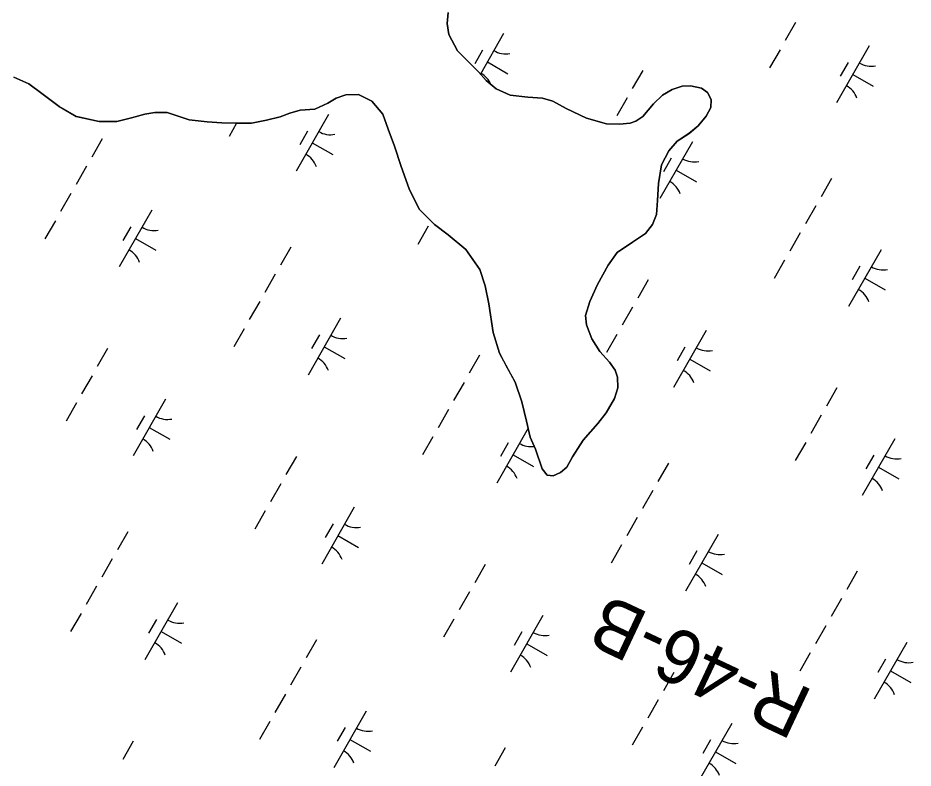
# Model space of a CAD drawing. Extents: x 3930721 to 3950824, y 220441 to 242861.
# Drawn here: x 3936788 to 3937473, y 225396 to 225970 of the extents above; entities that cross this region are included whole.
import ezdxf

# ---------------------------------------------------------------- set-up
doc = ezdxf.new("R2010")
doc.units = 0
for name, color, linetype in [('V-RIVR-RANG-IDEN', 7, 'Continuous'), ('V-TOPO-SHOR', 7, 'Continuous'), ('V-WETL-SWMP', 7, 'Continuous')]:
    doc.layers.add(name, color=color, linetype=linetype)

msp = doc.modelspace()

# ---------------------------------------------------------------- linework, layer by layer
at = {"layer": 'V-TOPO-SHOR'}
for points in [[(3937177.41, 225661.28), (3937180.22, 225648.96), (3937184.22, 225639.84), (3937189.42, 225624.75), (3937193.02, 225619.99), (3937197.79, 225619.6), (3937203.34, 225622), (3937208.1, 225625.99), (3937212.45, 225633.95), (3937220.76, 225646.69), (3937231.85, 225659.44), (3937238.19, 225667.8), (3937244.52, 225678.54), (3937247.28, 225686.9), (3937246.86, 225694.84), (3937245.25, 225700.4), (3937240.87, 225706.35), (3937233.29, 225714.67), (3937227.31, 225724.2), (3937223.3, 225734.92), (3937222.49, 225742.06), (3937225.64, 225752.8), (3937231.57, 225765.93), (3937239.87, 225780.66), (3937246.6, 225790.21), (3937258.5, 225798.19), (3937268.42, 225804.98), (3937273.57, 225811.74), (3937276.73, 225819.3), (3937277.49, 225830.03), (3937278.25, 225843.15), (3937280.6, 225857.46), (3937286.13, 225868.21), (3937292.47, 225875.38), (3937301.6, 225881.36), (3937308.73, 225887.34), (3937314.67, 225894.51), (3937318.23, 225901.28), (3937318.61, 225907.24), (3937315.81, 225912.79), (3937311.04, 225915.96), (3937302.69, 225917.92), (3937296.33, 225917.51), (3937288.79, 225915.1), (3937281.25, 225910.71), (3937274.51, 225903.94), (3937266.19, 225894.38), (3937261.04, 225890.79), (3937256.67, 225889.19), (3937248.33, 225888.37), (3937238.39, 225888.74), (3937223.28, 225893.07), (3937207.76, 225900.58), (3937197.41, 225906.12), (3937189.46, 225908.48), (3937178.33, 225909.24), (3937164.82, 225910.8), (3937154.07, 225915.54), (3937146.51, 225921.88), (3937140.53, 225928.62), (3937131.76, 225937.33), (3937124.59, 225944.47), (3937117.8, 225957.17), (3937116.59, 225965.51), (3937117.36, 225973.86)], [(3936785.28, 225924.49), (3936796.82, 225919.35), (3936806.77, 225911.83), (3936819.91, 225901.93), (3936833.04, 225894.41), (3936850.54, 225890.49), (3936864.05, 225890.52), (3936875.17, 225893.33), (3936885.5, 225896.14), (3936893.04, 225897.36), (3936902.58, 225897.38), (3936910.93, 225894.62), (3936919.28, 225891.86), (3936933.2, 225890.31), (3936944.33, 225889.54), (3936954.66, 225889.17), (3936966.98, 225889.21), (3936978.5, 225891.62), (3936988.82, 225894.03), (3936996.36, 225896.84), (3937004.3, 225899.24), (3937015.43, 225900.07), (3937025.35, 225904.46), (3937031.7, 225908.46), (3937039.24, 225910.86), (3937048.78, 225911.28), (3937059.12, 225906.15), (3937067.5, 225896.23), (3937071.5, 225884.72), (3937076.31, 225871.62), (3937081.51, 225856.13), (3937087.52, 225839.06), (3937095.11, 225823.58), (3937107.06, 225811.7), (3937117.42, 225803.78), (3937130.96, 225792.68), (3937141.73, 225777.22), (3937145.73, 225764.91), (3937148.56, 225751.01), (3937151.79, 225729.16), (3937156.6, 225713.28), (3937162.59, 225702.17), (3937168.58, 225691.06), (3937173.79, 225675.97), (3937177.41, 225661.28)]]:
    msp.add_lwpolyline(points, dxfattribs=at)
at = {"layer": 'V-WETL-SWMP'}
for p, q in [((3937117.36, 225973.86), (3937116.59, 225965.51)), ((3937116.59, 225965.51), (3937117.8, 225957.17)), ((3937383.15, 225966.31), (3937375.2, 225952.43)), ((3937117.8, 225957.17), (3937124.59, 225944.47)), ((3937159.81, 225957.75), (3937142.11, 225926.83)), ((3937439.35, 225948.3), (3937414.5, 225904.91)), ((3937124.59, 225944.47), (3937140.53, 225928.62)), ((3937143.68, 225945.1), (3937137.71, 225934.68)), ((3937371.23, 225945.48), (3937363.27, 225931.6)), ((3937147.39, 225936.06), (3937163.01, 225927.11)), ((3937423.21, 225935.64), (3937417.25, 225925.23)), ((3937140.53, 225928.62), (3937146.51, 225921.88)), ((3937266.18, 225929.58), (3937258.23, 225915.7)), ((3936796.82, 225919.35), (3936785.28, 225924.49)), ((3937146.51, 225921.88), (3937154.07, 225915.54)), ((3937426.92, 225926.6), (3937442.54, 225917.66)), ((3936806.77, 225911.83), (3936796.82, 225919.35)), ((3937154.07, 225915.54), (3937164.82, 225910.8)), ((3937281.25, 225910.71), (3937288.79, 225915.1)), ((3937288.79, 225915.1), (3937296.33, 225917.51)), ((3937296.33, 225917.51), (3937302.69, 225917.92)), ((3937302.69, 225917.92), (3937311.04, 225915.96)), ((3937311.04, 225915.96), (3937315.82, 225912.79)), ((3936819.91, 225901.93), (3936806.77, 225911.83)), ((3937031.7, 225908.46), (3937025.35, 225904.46)), ((3937039.24, 225910.86), (3937031.7, 225908.46)), ((3937048.78, 225911.28), (3937039.24, 225910.86)), ((3937059.12, 225906.14), (3937048.78, 225911.28)), ((3937164.82, 225910.8), (3937178.33, 225909.24)), ((3937178.33, 225909.24), (3937189.46, 225908.48)), ((3937189.46, 225908.48), (3937197.41, 225906.12)), ((3937254.26, 225908.76), (3937246.31, 225894.87)), ((3937274.51, 225903.94), (3937281.25, 225910.71)), ((3937315.82, 225912.79), (3937318.61, 225907.24)), ((3937318.61, 225907.24), (3937318.23, 225901.28)), ((3936833.05, 225894.41), (3936819.91, 225901.93)), ((3937025.35, 225904.46), (3937015.43, 225900.07)), ((3937067.5, 225896.23), (3937059.12, 225906.14)), ((3937197.41, 225906.12), (3937207.76, 225900.58)), ((3937207.76, 225900.58), (3937223.28, 225893.07)), ((3937266.19, 225894.38), (3937274.51, 225903.94)), ((3937318.23, 225901.28), (3937314.67, 225894.51)), ((3936850.54, 225890.49), (3936833.05, 225894.41)), ((3936875.17, 225893.33), (3936864.05, 225890.52)), ((3936885.5, 225896.14), (3936875.17, 225893.33)), ((3936893.04, 225897.35), (3936885.5, 225896.14)), ((3936902.58, 225897.38), (3936893.04, 225897.35)), ((3936919.28, 225891.86), (3936902.58, 225897.38)), ((3936988.82, 225894.03), (3936978.5, 225891.62)), ((3936996.36, 225896.84), (3936988.82, 225894.03)), ((3937004.3, 225899.24), (3936996.36, 225896.84)), ((3937025.95, 225895.86), (3937001.1, 225852.47)), ((3937015.43, 225900.07), (3937004.3, 225899.24)), ((3937071.5, 225884.72), (3937067.5, 225896.23)), ((3937261.04, 225890.79), (3937266.19, 225894.38)), ((3937314.67, 225894.51), (3937308.73, 225887.34)), ((3936864.05, 225890.52), (3936850.54, 225890.49)), ((3936933.2, 225890.31), (3936919.28, 225891.86)), ((3936944.33, 225889.54), (3936933.2, 225890.31)), ((3936954.66, 225889.17), (3936944.33, 225889.54)), ((3936955.61, 225889.18), (3936949.87, 225879.16)), ((3936966.98, 225889.21), (3936954.66, 225889.17)), ((3936978.5, 225891.62), (3936966.98, 225889.21)), ((3937223.28, 225893.07), (3937238.39, 225888.74)), ((3937238.39, 225888.74), (3937248.33, 225888.37)), ((3937248.33, 225888.37), (3937256.67, 225889.19)), ((3937256.67, 225889.19), (3937261.04, 225890.79)), ((3937308.73, 225887.34), (3937301.59, 225881.36)), ((3937009.81, 225883.21), (3937003.85, 225872.79)), ((3937076.31, 225871.62), (3937071.5, 225884.72)), ((3937301.59, 225881.36), (3937292.47, 225875.38)), ((3936852.78, 225877.15), (3936844.83, 225863.26)), ((3937013.52, 225874.17), (3937029.14, 225865.22)), ((3937304.16, 225875.08), (3937279.31, 225831.7)), ((3937292.47, 225875.38), (3937286.13, 225868.21)), ((3937081.51, 225856.13), (3937076.31, 225871.62)), ((3937286.13, 225868.21), (3937280.6, 225857.46)), ((3937288.02, 225862.43), (3937282.05, 225852.02)), ((3936840.86, 225856.32), (3936832.9, 225842.44)), ((3937087.52, 225839.06), (3937081.51, 225856.13)), ((3937280.6, 225857.46), (3937278.25, 225843.15)), ((3937291.73, 225853.39), (3937307.35, 225844.44)), ((3937410.53, 225846.92), (3937402.57, 225833.03)), ((3937095.11, 225823.58), (3937087.52, 225839.06)), ((3937278.25, 225843.15), (3937277.49, 225830.03)), ((3936828.93, 225835.5), (3936820.98, 225821.61)), ((3937277.49, 225830.03), (3937276.73, 225819.3)), ((3937398.6, 225826.09), (3937390.65, 225812.21)), ((3936890.75, 225822.65), (3936865.91, 225779.26)), ((3937107.06, 225811.7), (3937095.11, 225823.58)), ((3937276.73, 225819.3), (3937273.57, 225811.74)), ((3936817, 225814.67), (3936809.05, 225800.79)), ((3937117.42, 225803.78), (3937107.06, 225811.7)), ((3937273.57, 225811.74), (3937268.42, 225804.98)), ((3936874.62, 225810), (3936868.65, 225799.58)), ((3937102.17, 225810.38), (3937094.21, 225796.5)), ((3937268.42, 225804.98), (3937258.5, 225798.19)), ((3937386.67, 225805.27), (3937378.72, 225791.38)), ((3936878.33, 225800.95), (3936893.95, 225792.01)), ((3937130.96, 225792.68), (3937117.42, 225803.78)), ((3937258.5, 225798.19), (3937246.6, 225790.21)), ((3936997.12, 225794.48), (3936989.17, 225780.6)), ((3937141.73, 225777.22), (3937130.96, 225792.68)), ((3937448.5, 225792.42), (3937423.65, 225749.03)), ((3937246.6, 225790.21), (3937239.87, 225780.66)), ((3937374.74, 225784.44), (3937366.79, 225770.56)), ((3937145.73, 225764.91), (3937141.73, 225777.22)), ((3937239.87, 225780.66), (3937231.57, 225765.93)), ((3937432.36, 225779.77), (3937426.4, 225769.35)), ((3936985.2, 225773.66), (3936977.25, 225759.77)), ((3937436.07, 225770.72), (3937451.69, 225761.78)), ((3937148.55, 225751.01), (3937145.73, 225764.91)), ((3937231.57, 225765.93), (3937225.64, 225752.8)), ((3937270.36, 225769.37), (3937262.41, 225755.48)), ((3936973.27, 225752.83), (3936965.32, 225738.95)), ((3937151.79, 225729.16), (3937148.55, 225751.01)), ((3937225.64, 225752.8), (3937222.49, 225742.07)), ((3937258.44, 225748.54), (3937250.48, 225734.66)), ((3937035.1, 225739.98), (3937010.25, 225696.59)), ((3937222.49, 225742.07), (3937223.3, 225734.92)), ((3936961.34, 225732), (3936953.39, 225718.12)), ((3937156.6, 225713.28), (3937151.79, 225729.16)), ((3937223.3, 225734.92), (3937227.31, 225724.2)), ((3937314.63, 225730.53), (3937289.78, 225687.14)), ((3937018.96, 225727.33), (3937012.99, 225716.92)), ((3937227.31, 225724.2), (3937233.29, 225714.68)), ((3937246.51, 225727.71), (3937238.56, 225713.83)), ((3936856.96, 225716.93), (3936849.01, 225703.05)), ((3937022.67, 225718.29), (3937038.29, 225709.34)), ((3937298.49, 225717.87), (3937292.53, 225707.46)), ((3937141.47, 225711.82), (3937133.51, 225697.93)), ((3937168.58, 225691.06), (3937156.6, 225713.28)), ((3937233.29, 225714.68), (3937240.87, 225706.35)), ((3937302.21, 225708.83), (3937317.83, 225699.89)), ((3937240.87, 225706.35), (3937245.25, 225700.4)), ((3936845.03, 225696.1), (3936837.08, 225682.22)), ((3937245.25, 225700.4), (3937246.86, 225694.84)), ((3937246.86, 225694.84), (3937247.28, 225686.9)), ((3937129.54, 225690.99), (3937121.59, 225677.11)), ((3937173.79, 225675.97), (3937168.58, 225691.06)), ((3937247.28, 225686.9), (3937244.52, 225678.54)), ((3937414.7, 225686.7), (3937406.75, 225672.82)), ((3936833.11, 225675.28), (3936825.15, 225661.39)), ((3936901.23, 225678.09), (3936876.38, 225634.7)), ((3937177.41, 225661.28), (3937173.79, 225675.97)), ((3937244.52, 225678.54), (3937238.19, 225667.8)), ((3937117.61, 225670.16), (3937109.66, 225656.28)), ((3937238.19, 225667.8), (3937231.85, 225659.44)), ((3936885.09, 225665.44), (3936879.13, 225655.02)), ((3937180.22, 225648.97), (3937177.41, 225661.28)), ((3937402.78, 225665.87), (3937394.83, 225651.99)), ((3936888.8, 225656.4), (3936904.42, 225647.45)), ((3937178.63, 225655.91), (3937154.59, 225613.93)), ((3937231.85, 225659.44), (3937220.76, 225646.69)), ((3937105.68, 225649.34), (3937097.73, 225635.45)), ((3937184.22, 225639.84), (3937180.22, 225648.97)), ((3937458.97, 225647.86), (3937434.12, 225604.47)), ((3937163.3, 225644.66), (3937157.34, 225634.25)), ((3937220.76, 225646.69), (3937212.45, 225633.95)), ((3937390.85, 225645.05), (3937382.9, 225631.16)), ((3937001.3, 225634.26), (3936993.35, 225620.38)), ((3937167.01, 225635.62), (3937182.63, 225626.68)), ((3937189.42, 225624.75), (3937184.22, 225639.84)), ((3937212.45, 225633.95), (3937208.1, 225625.99)), ((3937442.83, 225635.21), (3937436.87, 225624.79)), ((3937285.81, 225629.15), (3937277.86, 225615.27)), ((3937193.01, 225619.99), (3937189.42, 225624.75)), ((3937197.78, 225619.61), (3937193.01, 225619.99)), ((3937203.34, 225622), (3937197.78, 225619.61)), ((3937208.1, 225625.99), (3937203.34, 225622)), ((3937446.55, 225626.17), (3937462.17, 225617.22)), ((3936989.38, 225613.44), (3936981.42, 225599.55)), ((3937273.88, 225608.32), (3937265.93, 225594.44)), ((3936977.45, 225592.61), (3936969.5, 225578.73)), ((3937045.57, 225595.42), (3937020.72, 225552.04)), ((3937261.95, 225587.5), (3937254, 225573.61)), ((3937029.43, 225582.77), (3937023.47, 225572.36)), ((3936872.41, 225576.71), (3936864.45, 225562.83)), ((3937033.15, 225573.73), (3937048.77, 225564.79)), ((3937323.78, 225574.65), (3937298.93, 225531.26)), ((3937250.02, 225566.67), (3937242.07, 225552.79)), ((3937307.64, 225562), (3937301.68, 225551.58)), ((3936860.48, 225555.89), (3936852.53, 225542)), ((3937145.64, 225551.6), (3937137.69, 225537.71)), ((3937311.35, 225552.96), (3937326.97, 225544.01)), ((3937430.15, 225546.48), (3937422.2, 225532.6)), ((3936848.55, 225535.06), (3936840.6, 225521.18)), ((3937133.72, 225530.77), (3937125.77, 225516.89)), ((3937418.22, 225525.66), (3937410.27, 225511.77)), ((3936910.38, 225522.21), (3936885.53, 225478.83)), ((3936836.62, 225514.23), (3936828.67, 225500.35)), ((3937121.79, 225509.95), (3937113.84, 225496.06)), ((3937189.91, 225512.76), (3937165.06, 225469.37)), ((3936894.24, 225509.56), (3936888.28, 225499.15)), ((3937406.29, 225504.83), (3937398.34, 225490.95)), ((3936897.95, 225500.52), (3936913.57, 225491.57)), ((3937173.77, 225500.11), (3937167.81, 225489.69)), ((3937016.75, 225494.05), (3937008.8, 225480.16)), ((3937177.49, 225491.06), (3937193.11, 225482.12)), ((3937468.12, 225491.98), (3937443.27, 225448.6)), ((3937394.37, 225484), (3937386.41, 225470.12)), ((3937451.98, 225479.33), (3937446.02, 225468.92)), ((3937004.82, 225473.22), (3936996.87, 225459.34)), ((3937289.99, 225468.93), (3937282.03, 225455.05)), ((3937455.7, 225470.29), (3937471.32, 225461.34)), ((3936992.89, 225452.39), (3936984.94, 225438.51)), ((3937278.06, 225448.11), (3937270.11, 225434.22)), ((3937054.72, 225439.55), (3937029.87, 225396.16)), ((3936980.96, 225431.57), (3936973.01, 225417.68)), ((3937334.25, 225430.09), (3937309.4, 225386.7)), ((3937038.58, 225426.89), (3937032.62, 225416.48)), ((3937266.13, 225427.28), (3937258.18, 225413.4)), ((3936876.58, 225416.5), (3936868.63, 225402.61)), ((3937042.29, 225417.85), (3937057.91, 225408.91)), ((3937318.11, 225417.44), (3937312.15, 225407.03)), ((3937161.09, 225411.38), (3937153.14, 225397.5)), ((3937321.83, 225408.4), (3937337.45, 225399.45))]:
    msp.add_line(p, q, dxfattribs=at)
for centre, start, end in [((3937161.32, 225959.91), 239.42788, 280.97154), ((3937440.86, 225950.45), 239.42788, 280.97154), ((3937133.87, 225911.97), 23.10442, 60.97154), ((3937413.4, 225902.51), 19.42788, 60.97154), ((3937027.46, 225898.02), 239.42788, 280.97154), ((3937000, 225850.08), 19.42788, 60.97154), ((3937305.66, 225877.24), 239.42788, 280.97154), ((3937278.21, 225829.3), 19.42788, 60.97154), ((3936892.26, 225824.81), 239.42788, 280.97154), ((3936864.81, 225776.87), 19.42788, 60.97154), ((3937450.01, 225794.58), 239.42788, 280.97154), ((3937422.55, 225746.64), 19.42788, 60.97154), ((3937036.6, 225742.14), 239.42788, 280.97154), ((3937316.14, 225732.68), 239.42788, 280.97154), ((3937009.15, 225694.2), 19.42788, 60.97154), ((3937288.68, 225684.75), 19.42788, 60.97154), ((3936902.74, 225680.25), 239.42788, 280.97154), ((3936875.28, 225632.31), 19.42788, 60.97154), ((3937180.95, 225659.47), 239.42788, 277.57384), ((3937460.48, 225650.02), 239.42788, 280.97154), ((3937153.49, 225611.54), 19.42788, 60.97154), ((3937433.03, 225602.08), 19.42788, 60.97154), ((3937047.08, 225597.58), 239.42788, 280.97154), ((3937019.62, 225549.64), 19.42788, 60.97154), ((3937325.29, 225576.81), 239.42788, 280.97154), ((3937297.83, 225528.87), 19.42788, 60.97154), ((3936911.89, 225524.37), 239.42788, 280.97154), ((3937191.42, 225514.92), 239.42788, 280.97154), ((3936884.43, 225476.43), 19.42788, 60.97154), ((3937163.97, 225466.98), 19.42788, 60.97154), ((3937469.63, 225494.14), 239.42788, 280.97154), ((3937442.17, 225446.2), 19.42788, 60.97154), ((3937056.23, 225441.7), 239.42788, 280.97154), ((3937335.76, 225432.25), 239.42788, 280.97154), ((3937028.77, 225393.77), 19.42788, 60.97154), ((3937308.31, 225384.31), 19.42788, 60.97154)]:
    msp.add_arc(centre, 17.62, start, end, dxfattribs=at)

# ---------------------------------------------------------------- texts
at = {"layer": 'V-RIVR-RANG-IDEN'}
msp.add_text('R-46-B', height=41.5, rotation=154.7914, dxfattribs=at).set_placement((3937397.94, 225454.68))

doc.saveas('drawing.dxf')
